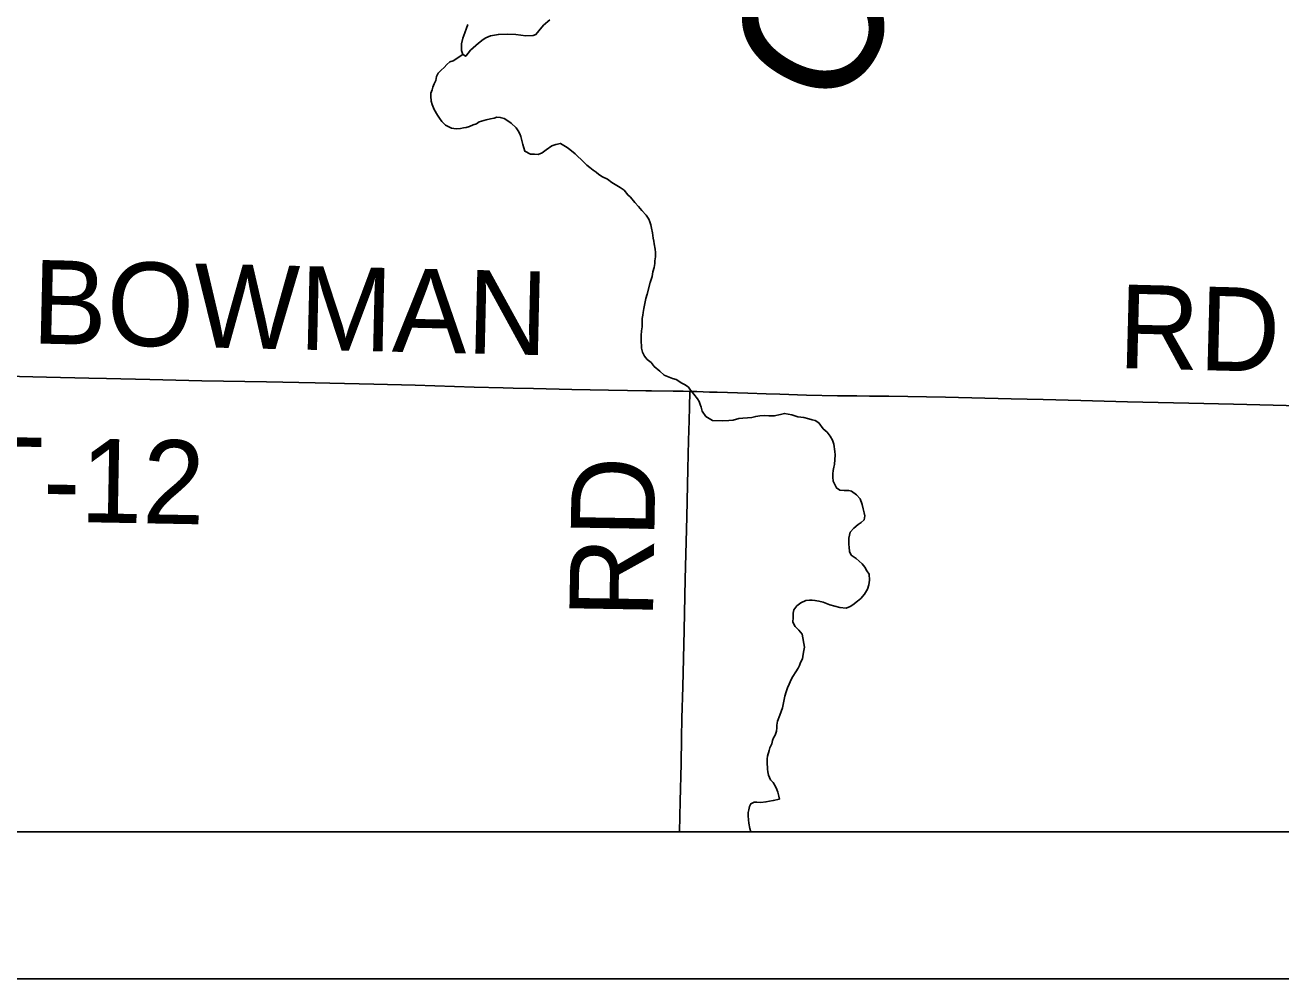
# Model space of a CAD drawing. Extents: x 0 to 34, y 0 to 22.
# Drawn here: x 24.806 to 25.659, y 14 to 14.648 of the extents above; entities that cross this region are included whole.
import ezdxf

# ---------------------------------------------------------------- set-up
doc = ezdxf.new("R2010")
doc.units = 0
for name, color, linetype in [('GM_X_Minor_Lake', 7, 'Continuous'), ('GM_X_Minor_River', 7, 'Continuous'), ('GM_X_Minor_River_Text', 7, 'Continuous'), ('GM_X_Township_Road', 7, 'Continuous'), ('GM_X_Township_Road_Text', 7, 'Continuous'), ('SH_Data', 7, 'Continuous')]:
    doc.layers.add(name, color=color, linetype=linetype)

msp = doc.modelspace()

# ---------------------------------------------------------------- linework, layer by layer
at = {"layer": 'GM_X_Minor_Lake'}
msp.add_lwpolyline([(25.10709, 14.64848), (25.10624, 14.64585), (25.105, 14.64285), (25.10374, 14.63908), (25.10286, 14.63531), (25.10278, 14.63265), (25.10271, 14.63075), (25.10377, 14.62805), (25.10564, 14.62685), (25.10881, 14.63093), (25.1143, 14.63569), (25.11743, 14.63825), (25.11937, 14.63933), (25.12246, 14.64075), (25.12782, 14.64171), (25.13392, 14.64189), (25.13963, 14.6417), (25.14645, 14.64072), (25.15141, 14.64093), (25.15333, 14.64163), (25.15532, 14.64423), (25.15849, 14.64793), (25.16279, 14.65159)], dxfattribs=at)
msp.add_lwpolyline([(25.10709, 14.64848), (25.10624, 14.64585), (25.105, 14.64285), (25.10374, 14.63908), (25.10286, 14.63531), (25.10278, 14.63265), (25.10271, 14.63075), (25.10377, 14.62805), (25.10564, 14.62685), (25.10881, 14.63093), (25.1143, 14.63569), (25.11743, 14.63825), (25.11937, 14.63933), (25.12246, 14.64075), (25.12782, 14.64171), (25.13392, 14.64189), (25.13963, 14.6417), (25.14645, 14.64072), (25.15141, 14.64093), (25.15333, 14.64163), (25.15532, 14.64423), (25.15849, 14.64793), (25.16279, 14.65159)], dxfattribs=at)
at = {"layer": 'GM_X_Minor_River'}
for points in [[(25.10377, 14.62805), (25.09716, 14.6237), (25.09485, 14.62302), (25.09289, 14.62118), (25.09093, 14.61934), (25.08896, 14.61751), (25.08699, 14.61529), (25.08577, 14.61305), (25.08531, 14.6104), (25.08409, 14.60816), (25.08326, 14.6059), (25.08282, 14.60401), (25.08198, 14.60176), (25.08192, 14.59986), (25.0822, 14.59642), (25.08288, 14.59412), (25.0843, 14.59065), (25.08646, 14.58677), (25.08792, 14.58482), (25.08937, 14.58249), (25.09196, 14.58012), (25.09421, 14.57891), (25.09608, 14.57808), (25.09911, 14.5776), (25.10217, 14.57788), (25.10408, 14.5782), (25.106, 14.57852), (25.1083, 14.5792), (25.11062, 14.58027), (25.11293, 14.58095), (25.11488, 14.58241), (25.1195, 14.58378), (25.12256, 14.58444), (25.12486, 14.58474), (25.12678, 14.58544), (25.12907, 14.58536), (25.13171, 14.58452), (25.13432, 14.58291), (25.13656, 14.58131), (25.13988, 14.57816), (25.14134, 14.57621), (25.14242, 14.57427), (25.14312, 14.57234), (25.1438, 14.56966), (25.14448, 14.56697), (25.14516, 14.56467), (25.14585, 14.56236), (25.1496, 14.56033), (25.15226, 14.56025), (25.15492, 14.56016), (25.15762, 14.56121), (25.16036, 14.5634), (25.16425, 14.56594), (25.16695, 14.56699), (25.17001, 14.56765), (25.1745, 14.56484), (25.17636, 14.56363), (25.18007, 14.56047), (25.18598, 14.55495), (25.18782, 14.55298), (25.19006, 14.55139), (25.19228, 14.54941), (25.19415, 14.54821), (25.196, 14.54663), (25.19862, 14.54502), (25.20199, 14.54338), (25.20496, 14.541), (25.20833, 14.53899), (25.21057, 14.53777), (25.21318, 14.53579), (25.21574, 14.53266), (25.21759, 14.53107), (25.22053, 14.52755), (25.22311, 14.52481), (25.2253, 14.52207), (25.22825, 14.51893), (25.23007, 14.5162), (25.23077, 14.51428), (25.23147, 14.51235), (25.23178, 14.51006), (25.23244, 14.50699), (25.23276, 14.50508), (25.23308, 14.50317), (25.2334, 14.50126), (25.23372, 14.49934), (25.23437, 14.4959), (25.23468, 14.49361), (25.23458, 14.49056), (25.23411, 14.48792), (25.23405, 14.48602), (25.23359, 14.48337), (25.23273, 14.48035), (25.23225, 14.47733), (25.23098, 14.47318), (25.22882, 14.46526), (25.22796, 14.46225), (25.22751, 14.45998), (25.2266, 14.45545), (25.22614, 14.4528)], [(25.22614, 14.4528), (25.22608, 14.4509), (25.22562, 14.44863), (25.22551, 14.44521), (25.22544, 14.44293), (25.22498, 14.44028), (25.22488, 14.43724), (25.22482, 14.43534), (25.22473, 14.43268), (25.22504, 14.43039), (25.22498, 14.42849), (25.22566, 14.4258), (25.22709, 14.42309), (25.22892, 14.42075), (25.23153, 14.41876), (25.23372, 14.41602), (25.23743, 14.41286), (25.24039, 14.4101), (25.24378, 14.40884), (25.24603, 14.40801), (25.24867, 14.40716), (25.2524, 14.40475), (25.25465, 14.40354), (25.25689, 14.40194), (25.25835, 14.39999), (25.26054, 14.39726), (25.26311, 14.39413), (25.26419, 14.39219), (25.26489, 14.39026), (25.26559, 14.38834), (25.26627, 14.38565), (25.26882, 14.38214), (25.2733, 14.37933), (25.27977, 14.37912), (25.28435, 14.37935), (25.2874, 14.37963), (25.29124, 14.38064), (25.29392, 14.38094), (25.29697, 14.38121), (25.30003, 14.38149), (25.30272, 14.38216), (25.30539, 14.38246), (25.30883, 14.38273), (25.31149, 14.38264), (25.31339, 14.38257), (25.31529, 14.38251), (25.31952, 14.38351), (25.3222, 14.38418), (25.32713, 14.38326), (25.33128, 14.38198), (25.33545, 14.38146), (25.33885, 14.38059), (25.3411, 14.37976), (25.343, 14.37931), (25.34561, 14.3777), (25.34853, 14.3738), (25.35112, 14.37143), (25.35332, 14.3687), (25.35476, 14.36599), (25.35581, 14.36329), (25.35642, 14.35832), (25.35672, 14.35603), (25.35614, 14.34958), (25.3557, 14.3477), (25.35524, 14.34543), (25.35517, 14.34315), (25.3551, 14.34087), (25.35539, 14.3382), (25.35609, 14.33627), (25.35753, 14.33356), (25.35976, 14.33196), (25.36281, 14.33186), (25.36585, 14.33176), (25.36774, 14.33132), (25.37109, 14.32892), (25.37367, 14.32618), (25.37507, 14.32232), (25.37573, 14.31926), (25.37641, 14.31657), (25.37673, 14.31466), (25.37626, 14.31201), (25.3743, 14.31018), (25.37235, 14.30872), (25.36922, 14.30616), (25.36685, 14.30357), (25.36596, 14.29942), (25.3659, 14.29752), (25.36583, 14.29524), (25.36615, 14.29332), (25.36643, 14.29027), (25.3675, 14.28795), (25.37085, 14.28556), (25.37493, 14.282), (25.37675, 14.27966), (25.3782, 14.27733), (25.37965, 14.275), (25.3799, 14.2708), (25.37942, 14.26778), (25.37856, 14.26476), (25.37655, 14.2614), (25.37417, 14.25844)], [(25.37417, 14.25844), (25.37183, 14.25661), (25.3687, 14.25405), (25.36676, 14.25298), (25.36406, 14.25192), (25.35989, 14.25244), (25.35649, 14.25331), (25.35309, 14.25419), (25.35083, 14.25503), (25.34857, 14.25586), (25.34555, 14.25672), (25.3429, 14.25719), (25.341, 14.25725), (25.3391, 14.25731), (25.3368, 14.25701), (25.33333, 14.2556), (25.3306, 14.25341), (25.32861, 14.25081), (25.32815, 14.24855), (25.32806, 14.24551), (25.32796, 14.24247), (25.32938, 14.23937), (25.33197, 14.23701), (25.33417, 14.23427), (25.33579, 14.22547), (25.33534, 14.2232), (25.33488, 14.22055), (25.3344, 14.21752), (25.33317, 14.2149), (25.33235, 14.21302), (25.33153, 14.21115), (25.32992, 14.20854), (25.32792, 14.20556), (25.32671, 14.20332), (25.32547, 14.20032), (25.32424, 14.1977), (25.3234, 14.19506), (25.32254, 14.19205), (25.32167, 14.18865), (25.32076, 14.18411), (25.31908, 14.17922), (25.31743, 14.17509), (25.31696, 14.17245), (25.3169, 14.17055), (25.31683, 14.16827), (25.31598, 14.16563), (25.31478, 14.16377), (25.31396, 14.16189), (25.31351, 14.15963), (25.31228, 14.157), (25.31184, 14.15511), (25.31058, 14.15135), (25.31052, 14.14945), (25.31044, 14.14717), (25.31068, 14.1426), (25.311, 14.14069), (25.31131, 14.13839), (25.31273, 14.1353), (25.31457, 14.13334), (25.31601, 14.13063), (25.31709, 14.12869), (25.31779, 14.12676), (25.31846, 14.12408), (25.31878, 14.12216), (25.31456, 14.12116), (25.30958, 14.12019), (25.30614, 14.11992), (25.30348, 14.12001), (25.30158, 14.12007), (25.29926, 14.11901), (25.29844, 14.11713), (25.29799, 14.11486), (25.29754, 14.11298), (25.29747, 14.1107), (25.29777, 14.10802), (25.29807, 14.10573), (25.29873, 14.10228), (25.2993, 14.1)]]:
    msp.add_lwpolyline(points, dxfattribs=at)
at = {"layer": 'GM_X_Township_Road'}
for points in [[(23.51667, 18.40743), (23.51667, 14.1), (28.76735, 14.1), (28.77086, 14.31073), (28.79336, 15.31551), (28.8021, 16.36959)], [(24.7529, 14.41064), (24.77465, 14.41004), (24.8209, 14.40877), (24.8495, 14.40808), (24.8615, 14.40782), (24.89112, 14.40717), (24.92642, 14.40641), (24.97024, 14.40562), (25.0033, 14.40493), (25.04322, 14.40409), (25.07123, 14.40329), (25.11131, 14.40214), (25.13111, 14.40169), (25.13794, 14.40146), (25.15161, 14.40103), (25.17771, 14.40038), (25.20258, 14.40011), (25.21563, 14.39987), (25.22805, 14.39958), (25.23178, 14.3995), (25.24666, 14.39932), (25.25348, 14.39924), (25.25786, 14.39915)], [(25.25093, 14.1), (25.25143, 14.12071), (25.2519, 14.14618), (25.25225, 14.16358), (25.2525, 14.17725), (25.25314, 14.19837), (25.25408, 14.2369), (25.25482, 14.27169), (25.25587, 14.31394), (25.25655, 14.34625), (25.25685, 14.35618), (25.25708, 14.36588), (25.2574, 14.37936), (25.25761, 14.38843), (25.25786, 14.39915)], [(25.25786, 14.39915), (25.26276, 14.39904), (25.27131, 14.39875), (25.27419, 14.39862), (25.27648, 14.39861), (25.29741, 14.398), (25.30983, 14.39756), (25.31915, 14.39728), (25.33717, 14.39669), (25.35828, 14.3962), (25.36511, 14.3961), (25.3682, 14.39609), (25.37129, 14.39612), (25.37999, 14.396), (25.39304, 14.3959), (25.43156, 14.39517), (25.47631, 14.39403), (25.49806, 14.39358), (25.52353, 14.39295), (25.55532, 14.39216), (25.59685, 14.39113), (25.62731, 14.39052), (25.67205, 14.38934)]]:
    msp.add_lwpolyline(points, dxfattribs=at)
at = {"layer": 'SH_Data'}
for points in [[(23.41667, 21), (30.41667, 21), (30.41667, 14), (23.41667, 14)], [(23.51667, 20.9), (30.31667, 20.9), (30.31667, 14.1), (23.51667, 14.1)]]:
    msp.add_lwpolyline(points, close=True, dxfattribs=at)

# ---------------------------------------------------------------- texts
at = {"layer": 'GM_X_Minor_River_Text'}
msp.add_text('Creek', height=0.094752, rotation=61.17501, dxfattribs=at).set_placement((25.35997, 14.58457))
at = {"layer": 'GM_X_Township_Road_Text'}
for s, rotation, p in [('BOWMAN', 358.67971, (24.8106, 14.43178)), ('RD', 358.53108, (25.54852, 14.41508)), ('T-12', 358.94286, (24.77165, 14.31168)), ('RD', 89.01842, (25.2328, 14.24462))]:
    msp.add_text(s, height=0.056818, rotation=rotation, dxfattribs=at).set_placement(p)

doc.saveas('drawing.dxf')
